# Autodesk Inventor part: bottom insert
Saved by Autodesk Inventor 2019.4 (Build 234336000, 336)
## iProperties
Created: 2020-09
Part Number: bottom insert
Material: Generic
Document SubType Name: Modeling
Designer: Administrator
Density: 1 g/cm^3
Appearance: Default
Title: bottom insert
Author: Administrator
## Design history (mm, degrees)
feature "Body1"
body "Solid1"
